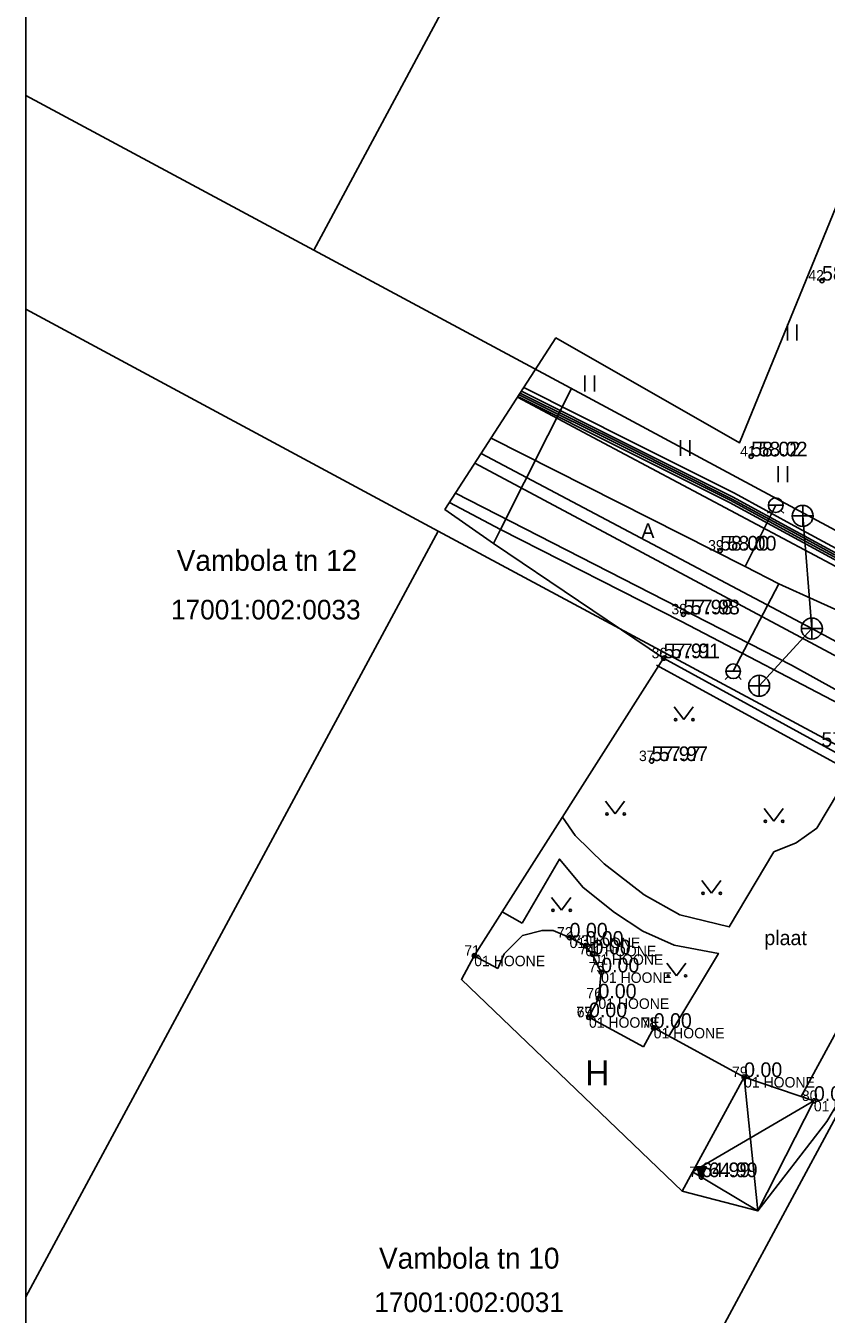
# Model space of a CAD drawing. Extents: x 640891 to 641083, y 6456526 to 6456669.
# Drawn here: x 640890.6 to 640928.8, y 6456556.9 to 6456618.4 of the extents above; entities that cross this region are included whole.
import ezdxf

# ---------------------------------------------------------------- set-up
doc = ezdxf.new("R2010")
doc.units = 0
for name, color, linetype in [('100koma2', 7, 'Continuous'), ('AED', 7, 'Continuous'), ('HALJASTUS', 7, 'Continuous'), ('HOONE', 7, 'Continuous'), ('HOONEDET', 7, 'Continuous'), ('KKAEV', 7, 'Continuous'), ('KORGUS', 7, 'Continuous'), ('KPKAABEL', 7, 'Continuous'), ('KTRASS', 7, 'Continuous'), ('MOOTKORG', 7, 'Continuous'), ('MOOTKORG_MUU', 7, 'Continuous'), ('MOOTMPUNKT', 7, 'Continuous'), ('MOOTNR', 7, 'Continuous'), ('MOOTPIIR', 7, 'Continuous'), ('MPKAABEL', 7, 'Continuous'), ('PIIR', 7, 'Continuous'), ('SITRASS', 7, 'Continuous'), ('SKTRASS', 7, 'Continuous'), ('TEE', 7, 'Continuous'), ('VKAEV', 7, 'Continuous'), ('VORMISTUS', 7, 'Continuous'), ('VTRASS', 7, 'Continuous')]:
    doc.layers.add(name, color=color, linetype=linetype)

msp = doc.modelspace()

# ---------------------------------------------------------------- linework, layer by layer
at = {"layer": 'AED'}
msp.add_line((640920.739, 6456587.89), (640930.051, 6456582.793), dxfattribs=at)
msp.add_lwpolyline([(640930.267, 6456583.186), (640921.076, 6456588.216)], dxfattribs=at)
msp.add_lwpolyline([(640930.267, 6456583.186), (640921.076, 6456588.216)], dxfattribs=at)
at = {"layer": 'HALJASTUS'}
for p, q in [((640926.988, 6456604.15), (640926.988, 6456603.388)), ((640927.443, 6456604.15), (640927.443, 6456603.388)), ((640917.318, 6456601.711), (640917.318, 6456600.95)), ((640917.773, 6456601.711), (640917.773, 6456600.95)), ((640921.875, 6456598.632), (640921.875, 6456597.871)), ((640922.33, 6456598.632), (640922.33, 6456597.871)), ((640926.545, 6456597.381), (640926.545, 6456596.619)), ((640927, 6456597.381), (640927, 6456596.619)), ((640921.584, 6456585.889), (640922.047, 6456585.282)), ((640922.047, 6456585.282), (640922.493, 6456585.889)), ((640918.301, 6456581.391), (640918.765, 6456580.785)), ((640918.765, 6456580.785), (640919.21, 6456581.391)), ((640925.877, 6456581.038), (640926.34, 6456580.431)), ((640926.34, 6456580.431), (640926.786, 6456581.038)), ((640922.897, 6456577.601), (640923.361, 6456576.994)), ((640923.361, 6456576.994), (640923.806, 6456577.601)), ((640915.726, 6456576.793), (640916.189, 6456576.186)), ((640916.189, 6456576.186), (640916.635, 6456576.793)), ((640921.231, 6456573.66), (640921.694, 6456573.053)), ((640921.694, 6456573.053), (640922.14, 6456573.66))]:
    msp.add_line(p, q, dxfattribs=at)
for centre in [(640921.646, 6456585.282), (640922.475, 6456585.282), (640918.364, 6456580.785), (640919.193, 6456580.785), (640925.939, 6456580.431), (640926.768, 6456580.431), (640922.959, 6456576.994), (640923.788, 6456576.994), (640915.788, 6456576.186), (640916.617, 6456576.186), (640921.293, 6456573.053), (640922.122, 6456573.053)]:
    msp.add_circle(centre, 0.055, dxfattribs=at)
at = {"layer": 'HOONE'}
for p, q in [((640912.029, 6456574.013), (640911.417, 6456572.885)), ((640912.029, 6456574.013), (640913.157, 6456573.4)), ((640917.509, 6456571.075), (640920.111, 6456569.663)), ((640920.111, 6456569.663), (640920.602, 6456570.567)), ((640924.921, 6456568.221), (640920.602, 6456570.567)), ((640924.921, 6456568.221), (640921.958, 6456562.765))]:
    msp.add_line(p, q, dxfattribs=at)
for points in [[(640913.157, 6456573.4), (640913.464, 6456574.095), (640914.339, 6456574.985), (640915.266, 6456575.217), (640915.801, 6456575.214), (640916.582, 6456574.879)], [(640917.509, 6456571.075), (640917.961, 6456571.975), (640918.091, 6456573.216), (640917.68, 6456574.078), (640917.338, 6456574.489), (640916.582, 6456574.879)], [(640924.921, 6456568.221), (640925.582, 6456561.827)], [(640922.46, 6456563.688), (640928.256, 6456567.083)]]:
    msp.add_lwpolyline(points, dxfattribs=at)
at = {"layer": 'HOONEDET'}
msp.add_lwpolyline([(640924.921, 6456568.221), (640928.256, 6456567.083), (640925.582, 6456561.827), (640922.46, 6456563.688)], dxfattribs=at)
at = {"layer": 'KKAEV'}
for p, q in [((640927.72, 6456594.51), (640927.72, 6456595.51)), ((640927.22, 6456595.01), (640928.22, 6456595.01)), ((640927.66, 6456589.63), (640928.66, 6456589.63)), ((640928.16, 6456589.13), (640928.16, 6456590.13)), ((640925.64, 6456586.4), (640925.64, 6456587.4)), ((640925.14, 6456586.9), (640926.14, 6456586.9))]:
    msp.add_line(p, q, dxfattribs=at)
for centre in [(640927.72, 6456595.01), (640928.16, 6456589.63), (640925.64, 6456586.9)]:
    msp.add_circle(centre, 0.5, dxfattribs=at)
at = {"layer": 'KORGUS'}
for p, q in [((640922.876, 6456563.441), (640922.629, 6456563.927)), ((640923.122, 6456563.927), (640922.629, 6456563.927)), ((640922.638, 6456563.911), (640922.981, 6456563.649)), ((640922.657, 6456563.927), (640922.993, 6456563.672)), ((640922.664, 6456563.86), (640922.97, 6456563.626)), ((640922.689, 6456563.809), (640922.958, 6456563.604)), ((640922.698, 6456563.927), (640923.004, 6456563.695)), ((640922.715, 6456563.757), (640922.947, 6456563.581)), ((640922.74, 6456563.927), (640923.016, 6456563.717)), ((640922.781, 6456563.927), (640923.027, 6456563.74)), ((640922.822, 6456563.927), (640923.039, 6456563.763)), ((640922.863, 6456563.927), (640923.05, 6456563.785)), ((640922.876, 6456563.441), (640923.122, 6456563.927)), ((640922.905, 6456563.927), (640923.062, 6456563.808)), ((640922.946, 6456563.927), (640923.073, 6456563.831)), ((640922.987, 6456563.927), (640923.085, 6456563.853)), ((640923.028, 6456563.927), (640923.096, 6456563.876)), ((640923.07, 6456563.927), (640923.108, 6456563.899)), ((640923.111, 6456563.927), (640923.119, 6456563.921)), ((640922.741, 6456563.706), (640922.935, 6456563.558)), ((640922.767, 6456563.655), (640922.924, 6456563.536)), ((640922.793, 6456563.604), (640922.912, 6456563.513)), ((640922.819, 6456563.553), (640922.901, 6456563.49)), ((640922.845, 6456563.502), (640922.89, 6456563.468)), ((640922.871, 6456563.451), (640922.878, 6456563.445))]:
    msp.add_line(p, q, dxfattribs=at)
for centre in [(640928.642, 6456606.243), (640925.257, 6456597.851), (640923.775, 6456593.355), (640922.023, 6456590.309), (640921.076, 6456588.216), (640920.498, 6456583.305), (640917.5, 6456571.076)]:
    msp.add_circle(centre, 0.1, dxfattribs=at)
at = {"layer": 'KPKAABEL'}
msp.add_lwpolyline([(640977.507, 6456566.281), (640976.27, 6456566.95), (640967.49, 6456572.43), (640959.27, 6456576.625), (640951.05, 6456580.82), (640939.86, 6456586.9), (640935.075, 6456589.63), (640930.29, 6456592.36), (640924.23, 6456595.65), (640919.26, 6456598.135), (640914.117, 6456600.706)], dxfattribs=at)
at = {"layer": 'KTRASS'}
for points in [[(640928.16, 6456589.63), (640912.359, 6456597.993)], [(640928.16, 6456589.63), (640927.72, 6456595.01)], [(640928.16, 6456589.63), (640925.64, 6456586.9)], [(640955.081, 6456575.091), (640928.16, 6456589.63)]]:
    msp.add_lwpolyline(points, dxfattribs=at)
at = {"layer": 'MOOTMPUNKT'}
for centre in [(640928.642, 6456606.243), (640925.257, 6456597.851), (640923.775, 6456593.355), (640922.023, 6456590.309), (640921.076, 6456588.216), (640920.498, 6456583.305), (640916.582, 6456574.879), (640917.338, 6456574.489), (640917.68, 6456574.078), (640912.029, 6456574.013), (640918.091, 6456573.216), (640917.961, 6456571.975), (640917.5, 6456571.076), (640917.509, 6456571.075), (640920.602, 6456570.567), (640924.921, 6456568.221), (640928.256, 6456567.083), (640922.876, 6456563.441)]:
    msp.add_circle(centre, 0.1, dxfattribs=at)
at = {"layer": 'MOOTPIIR'}
msp.add_lwpolyline([(640976.662, 6456538.007), (640959.29, 6456546.142), (640961.328, 6456555.553), (640965.053, 6456562.959), (640957.364, 6456564.816), (640935.712, 6456572.952), (640933.007, 6456573.069), (640928.881, 6456566.092), (640925.582, 6456561.827), (640921.958, 6456562.765), (640911.417, 6456572.885), (640912.029, 6456574.013), (640921.076, 6456588.216), (640912.945, 6456593.7), (640910.627, 6456595.318), (640915.929, 6456603.505), (640924.706, 6456598.502), (640938.233, 6456631.58)], dxfattribs=at)
at = {"layer": 'MPKAABEL'}
for points in [[(640914.173, 6456600.793), (640919.31, 6456598.225), (640924.28, 6456595.74), (640927.31, 6456594.095), (640930.34, 6456592.45), (640935.125, 6456589.72), (640939.91, 6456586.99), (640945.495, 6456583.945), (640951.08, 6456580.9), (640959.31, 6456576.71), (640967.54, 6456572.52), (640971.93, 6456569.78), (640976.32, 6456567.04), (640977.56, 6456566.369)], [(640977.608, 6456566.451), (640976.37, 6456567.12), (640971.98, 6456569.865), (640967.59, 6456572.61), (640959.355, 6456576.785), (640951.12, 6456580.96), (640945.54, 6456584.015), (640939.96, 6456587.07), (640935.175, 6456589.8), (640930.39, 6456592.53), (640927.355, 6456594.18), (640924.32, 6456595.83), (640919.35, 6456598.315), (640914.227, 6456600.876)], [(640977.66, 6456566.54), (640976.42, 6456567.21), (640972.03, 6456569.95), (640967.64, 6456572.69), (640959.395, 6456576.855), (640951.15, 6456581.02), (640945.58, 6456584.09), (640940.01, 6456587.16), (640935.225, 6456589.89), (640930.44, 6456592.62), (640927.405, 6456594.27), (640924.37, 6456595.92), (640919.4, 6456598.405), (640914.283, 6456600.963)], [(640914.394, 6456601.133), (640919.49, 6456598.58), (640924.46, 6456596.09), (640927.495, 6456594.445), (640930.53, 6456592.8), (640935.32, 6456590.07), (640940.11, 6456587.34), (640945.625, 6456584.22), (640951.14, 6456581.1), (640953.87, 6456579.745), (640956.6, 6456578.39), (640957.06, 6456579.17)]]:
    msp.add_lwpolyline(points, dxfattribs=at)
at = {"layer": 'PIIR'}
msp.add_lwpolyline([(640930.79, 6456593.51), (640904.36, 6456607.7), (640935.64, 6456665.95), (640960.76, 6456649.34)], close=True, dxfattribs=at)
for points in [[(640890.598, 6456615.08), (640904.36, 6456607.7), (640930.79, 6456593.51), (640957.22, 6456579.32), (640983.63, 6456565.13), (641002.905, 6456555.058)], [(640890.598, 6456604.875), (640910.31, 6456594.28), (640890.598, 6456557.721)], [(640993.023, 6456550.09), (640989.66, 6456551.83), (640963.18, 6456565.91), (640936.74, 6456580.1), (640910.31, 6456594.28), (640890.598, 6456604.875)], [(640890.598, 6456557.721), (640910.31, 6456594.28), (640936.74, 6456580.1), (640907.494, 6456525.865)], [(640907.494, 6456525.865), (640936.74, 6456580.1), (640963.18, 6456565.91), (640941.583, 6456525.865)]]:
    msp.add_lwpolyline(points, dxfattribs=at)
at = {"layer": 'SITRASS'}
for points in [[(640913.28, 6456594.36), (640916.67, 6456601.09)], [(640913.28, 6456594.36), (640910.841, 6456595.649)], [(640913.28, 6456594.36), (640912.945, 6456593.7)], [(640972.09, 6456562.42), (640955.26, 6456571.44), (640948.66, 6456575.39), (640939.25, 6456580.69), (640930.23, 6456585.64), (640921.93, 6456589.97), (640913.28, 6456594.36)]]:
    msp.add_lwpolyline(points, dxfattribs=at)
at = {"layer": 'SKTRASS'}
msp.add_lwpolyline([(640975.84, 6456563.446), (640963.035, 6456570.289), (640950.405, 6456577.04), (640931.282, 6456587.261), (640918.683, 6456593.994), (640912.062, 6456597.533)], dxfattribs=at)
at = {"layer": 'TEE'}
for points in [[(640977.461, 6456566.201), (640971.27, 6456569.61), (640958.74, 6456576.51), (640944.02, 6456584.555), (640929.3, 6456592.6), (640917.98, 6456598.615), (640914.098, 6456600.678)], [(640911.131, 6456596.096), (640915.765, 6456593.725), (640927.19, 6456587.88), (640941.825, 6456579.785), (640956.46, 6456571.69), (640969.135, 6456565.09), (640975.008, 6456562.032)], [(640927.641, 6456567.293), (640935.08, 6456580.963), (640930.423, 6456583.498), (640928.396, 6456580.096), (640927.415, 6456579.403), (640926.347, 6456578.97), (640924.212, 6456575.389), (640921.845, 6456575.967), (640920.143, 6456576.92), (640918.238, 6456578.393), (640916.853, 6456579.75), (640916.244, 6456580.63)], [(640914.314, 6456575.563), (640916.103, 6456578.624), (640917.228, 6456577.266), (640918.729, 6456576.082), (640920.085, 6456575.187), (640921.586, 6456574.523), (640923.692, 6456574.119), (640921.325, 6456570.174)], [(640914.314, 6456575.563), (640913.364, 6456576.109)]]:
    msp.add_lwpolyline(points, dxfattribs=at)
at = {"layer": 'VKAEV'}
for p, q in [((640926.183, 6456595.273), (640926.043, 6456595.133)), ((640926.08, 6456595.52), (640926.78, 6456595.52)), ((640926.677, 6456595.273), (640926.817, 6456595.133)), ((640924.153, 6456587.343), (640924.013, 6456587.203)), ((640924.05, 6456587.59), (640924.75, 6456587.59)), ((640924.647, 6456587.343), (640924.787, 6456587.203))]:
    msp.add_line(p, q, dxfattribs=at)
for centre in [(640926.43, 6456595.52), (640924.4, 6456587.59)]:
    msp.add_circle(centre, 0.35, dxfattribs=at)
at = {"layer": 'VORMISTUS'}
msp.add_line((640890.598, 6456525.865), (640890.598, 6456668.776), dxfattribs=at)
at = {"layer": 'VTRASS'}
for points in [[(640924.973, 6456592.595), (640912.834, 6456598.726)], [(640924.973, 6456592.595), (640926.43, 6456595.52)], [(640926.576, 6456591.762), (640924.973, 6456592.595)], [(640926.576, 6456591.762), (640924.4, 6456587.59)], [(640930.247, 6456590.108), (640926.576, 6456591.762)]]:
    msp.add_lwpolyline(points, dxfattribs=at)

# ---------------------------------------------------------------- texts
at = {"layer": '100koma2'}
for s, p in [('01 HOONE', (640916.582, 6456574.379)), ('01 HOONE', (640917.338, 6456573.989)), ('01 HOONE', (640912.029, 6456573.513)), ('01 HOONE', (640917.68, 6456573.578)), ('01 HOONE', (640918.091, 6456572.716)), ('01 HOONE', (640917.961, 6456571.475)), ('01 HOONE', (640917.509, 6456570.575)), ('01 HOONE', (640920.602, 6456570.067)), ('01 HOONE', (640924.921, 6456567.721)), ('01 KATUSEALL', (640928.256, 6456566.583))]:
    msp.add_text(s, height=0.5, dxfattribs=at).set_placement(p)
at = {"layer": 'HOONE'}
msp.add_text('H', height=1.2, dxfattribs=at).set_placement((640917.329, 6456567.821))
at = {"layer": 'KORGUS'}
for s, p in [('58.02', (640925.607, 6456597.851)), ('58.00', (640924.125, 6456593.355)), ('57.98', (640922.373, 6456590.309)), ('57.91', (640921.426, 6456588.216)), ('57.67', (640928.613, 6456583.985)), ('57.97', (640920.848, 6456583.305)), ('64.99', (640923.226, 6456563.441))]:
    msp.add_text(s, height=0.7, dxfattribs=at).set_placement(p)
at = {"layer": 'MOOTKORG'}
for s, p in [('58.21', (640928.642, 6456606.243)), ('58.02', (640925.257, 6456597.851)), ('58.00', (640923.775, 6456593.355)), ('57.98', (640922.023, 6456590.309)), ('57.91', (640921.076, 6456588.216)), ('57.97', (640920.498, 6456583.305)), ('0.00', (640916.582, 6456574.879)), ('0.00', (640917.338, 6456574.489)), ('0.00', (640917.68, 6456574.078)), ('0.00', (640918.091, 6456573.216)), ('0.00', (640917.961, 6456571.975)), ('0.00', (640917.509, 6456571.075)), ('0.00', (640920.602, 6456570.567)), ('0.00', (640924.921, 6456568.221)), ('0.00', (640928.256, 6456567.083))]:
    msp.add_text(s, height=0.7, dxfattribs=at).set_placement(p)
at = {"layer": 'MOOTKORG_MUU'}
msp.add_text('64.99', height=0.7, dxfattribs=at).set_placement((640922.876, 6456563.441))
at = {"layer": 'MOOTNR'}
for s, p in [('42', (640927.992, 6456606.243)), ('41', (640924.732, 6456597.851)), ('39', (640923.2, 6456593.355)), ('38', (640921.448, 6456590.309)), ('36', (640920.501, 6456588.216)), ('37', (640919.898, 6456583.305)), ('72', (640915.982, 6456574.879)), ('73', (640916.763, 6456574.489)), ('71', (640911.554, 6456574.013)), ('74', (640917.03, 6456574.078)), ('75', (640917.491, 6456573.216)), ('76', (640917.386, 6456571.975)), ('77', (640916.909, 6456571.075)), ('69', (640916.925, 6456571.076)), ('78', (640920.027, 6456570.567)), ('79', (640924.346, 6456568.221)), ('80', (640927.681, 6456567.083)), ('70', (640922.301, 6456563.441))]:
    msp.add_text(s, height=0.5, dxfattribs=at).set_placement(p)
at = {"layer": 'PIIR'}
for s, height, p in [('Vambola tn 12', 1.00002, (640897.812, 6456592.386)), ('17001:002:0033', 0.9375, (640897.535, 6456590.066)), ('Vambola tn 10', 1.00002, (640907.477, 6456559.073)), ('17001:002:0031', 0.9375, (640907.25, 6456557))]:
    msp.add_text(s, height=height, dxfattribs=at).set_placement(p)
at = {"layer": 'TEE'}
for s, p in [('A', (640920.015, 6456593.948)), ('plaat', (640925.889, 6456574.518))]:
    msp.add_text(s, height=0.7, dxfattribs=at).set_placement(p)

doc.saveas('drawing.dxf')
